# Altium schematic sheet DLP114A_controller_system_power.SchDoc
size 558 x 431 mm; Date: Not shown in title block; ApprovedBy: Not shown in title block; CheckedBy: Not shown in title block; Author: Not shown in title block; CompanyName: Not shown in title block; Engineer: Not shown in title block; Organization: Not shown in title block; Address1: Not shown in title block; Address2: Not shown in title block; Address3: Not shown in title block; Address4: Not shown in title block; DocumentNumber: 1; Revision: Use project parameter SCH_Rev; SheetNumber: 1; SheetTotal: 7; PageSetup: Record=PageOptions¦CenterHorizontal=True¦CenterVertical=True¦PrintScale=0.69¦XCorrection=1.00¦YCorrection=1.00¦PrintKind=0¦BorderSize=5000000¦LeftOffset=0¦BottomOffset=0¦Orientation=2¦PaperLength=1000¦PaperWidth=1000¦Scale=100¦PaperSource=15¦PrintQuality=600¦MediaType=1¦DitherType=10¦PaperKind=Letter¦PrintScaleMode=1
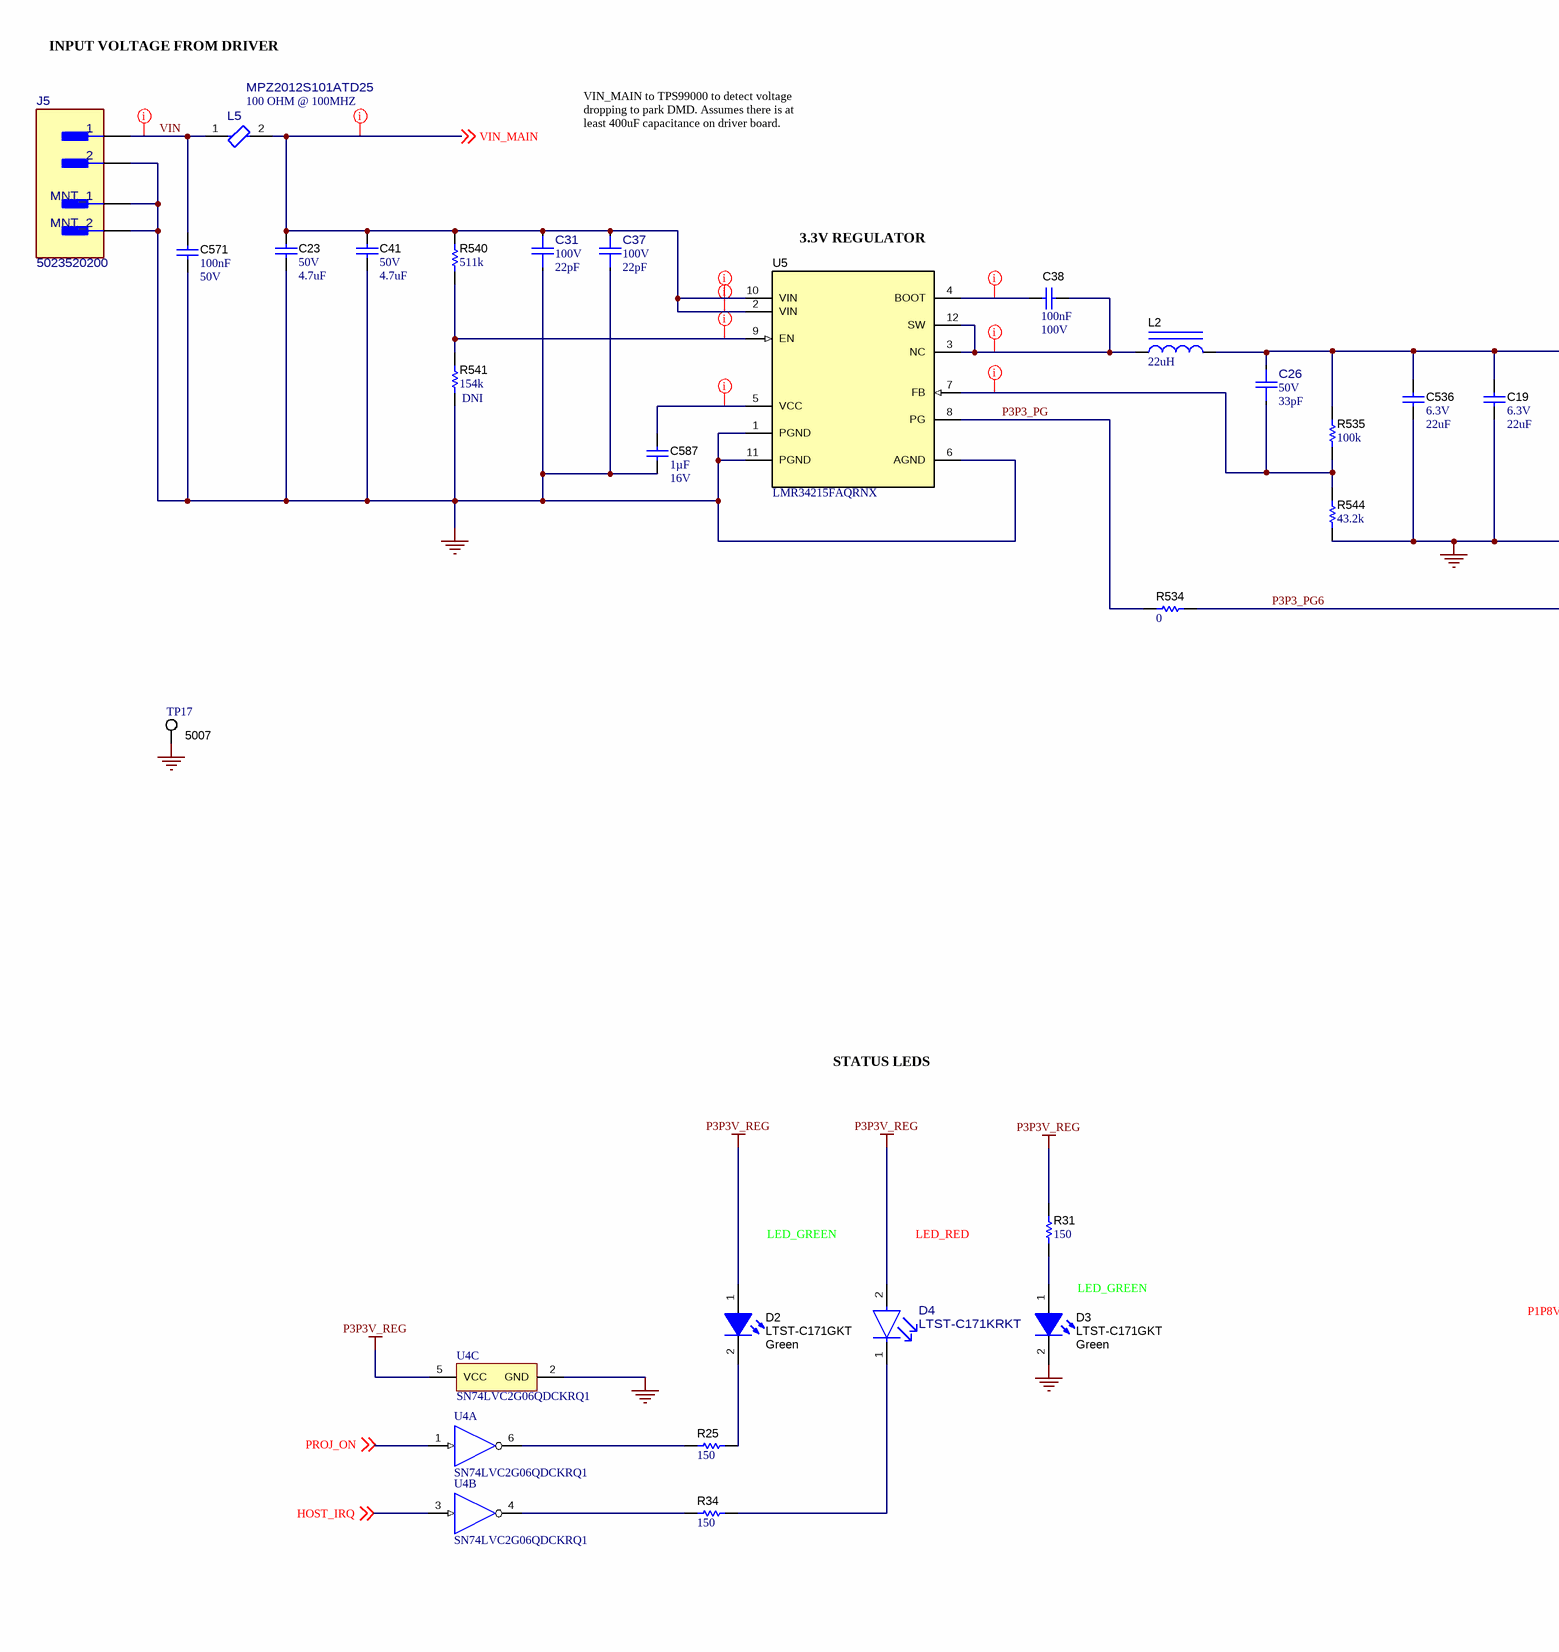
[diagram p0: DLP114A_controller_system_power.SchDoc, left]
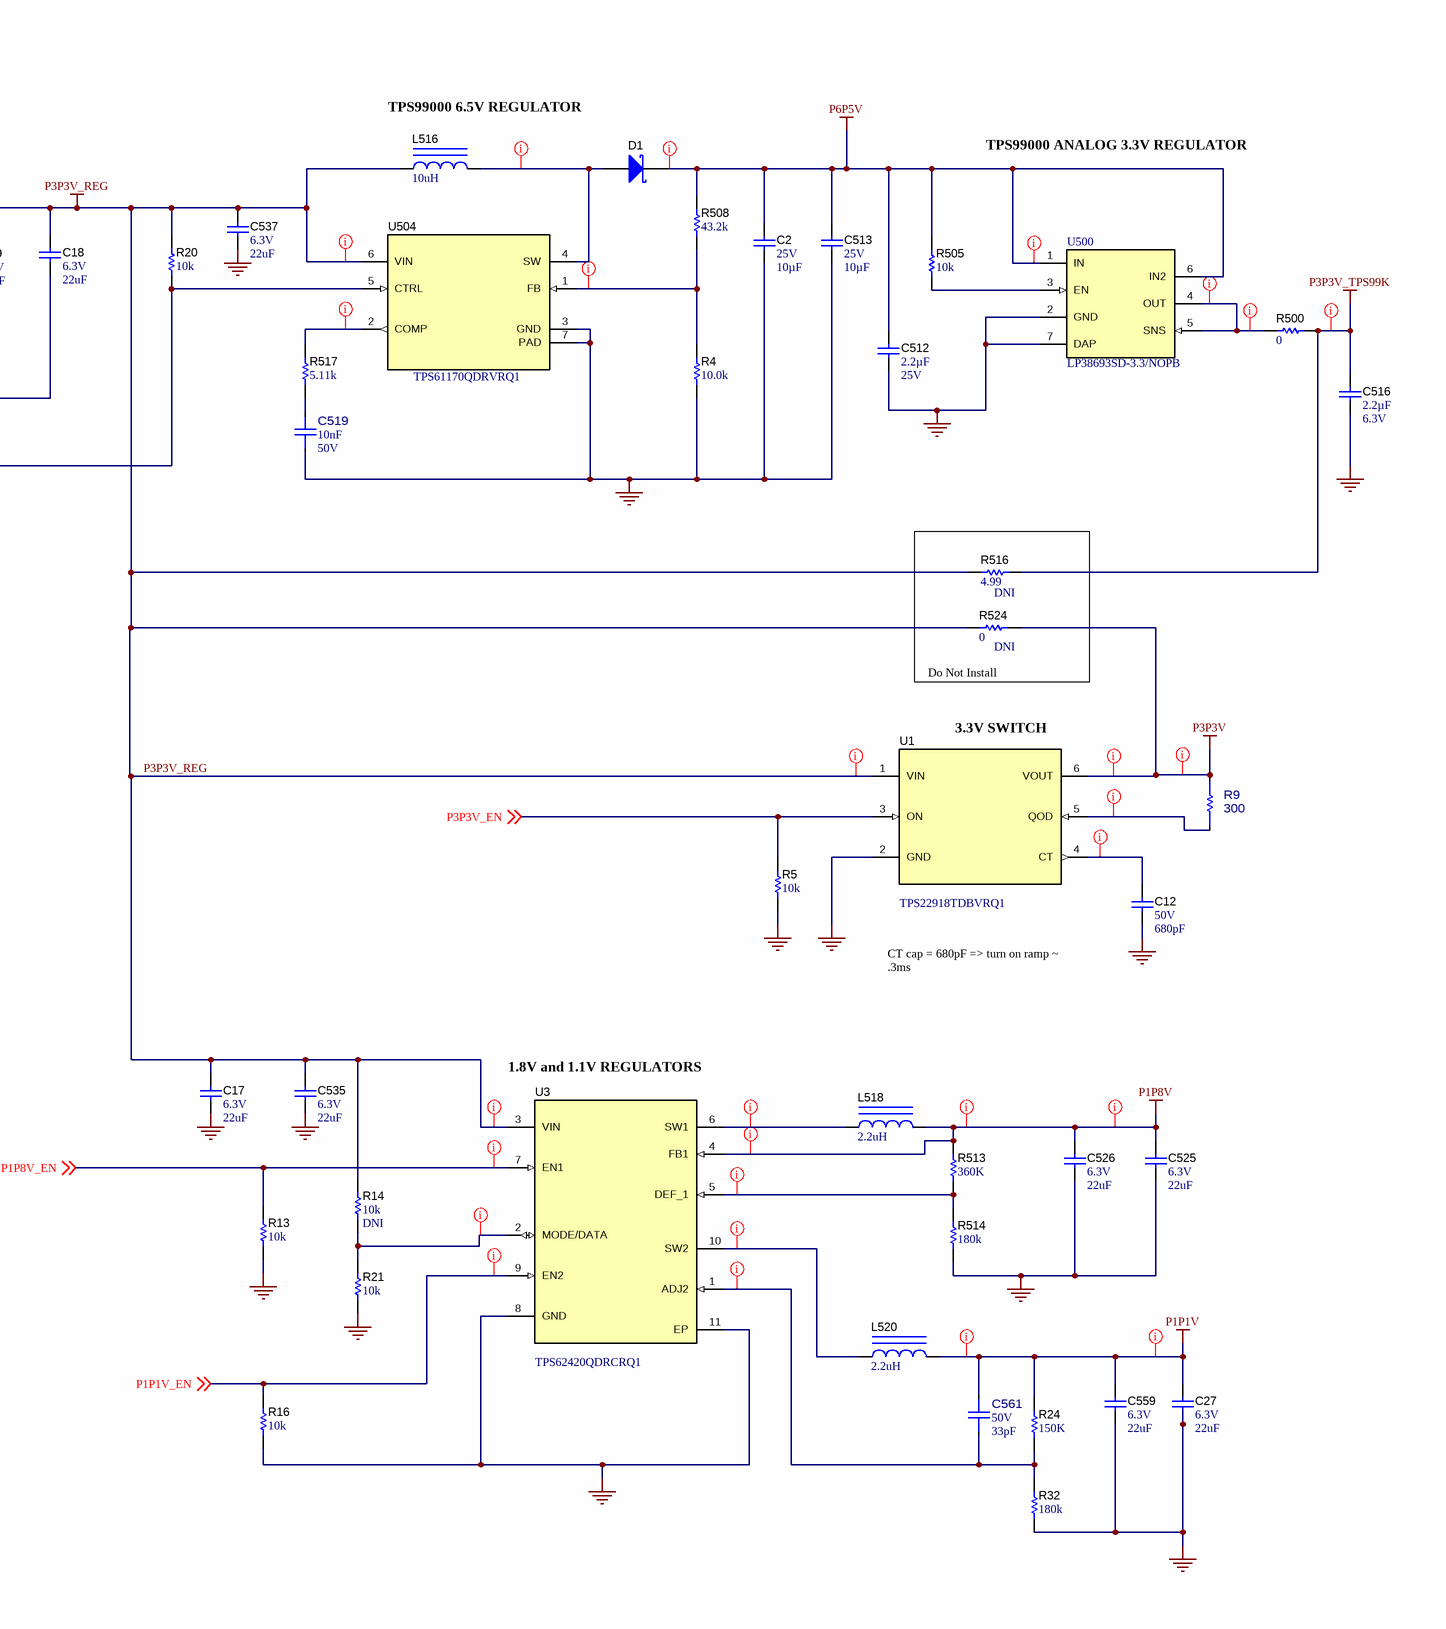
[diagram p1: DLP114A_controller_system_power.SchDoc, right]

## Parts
C2  VDC_V: 25V  ValueDisplayed: 10µF  [1206_180]  (hidden comment: C1206C106J3RACAUTO)
C12  VDC_V: 50V  ValueDisplayed: 680pF  [0402]  (hidden comment: GCM1555C1H681FA16D)
C17  VDC_V: 6.3V  ValueDisplayed: 22uF  [1206_180]  (hidden comment: GCM31CR70J226KE23L)
C18  VDC_V: 6.3V  ValueDisplayed: 22uF  [1206_180]  (hidden comment: GCM31CR70J226KE23L)
C19  VDC_V: 6.3V  ValueDisplayed: 22uF  [1206_180]  (hidden comment: GCM31CR70J226KE23L)
C23  VDC_V: 50V  ValueDisplayed: 4.7uF  [1210_280]  (hidden comment: CGA6P3X7R1H475M250AB)
C26  VDC_V: 50V  ValueDisplayed: 33pF  [FP-CGA3E2C0G1H330J080AA_0603-MFG]  (hidden comment: CGA3E2C0G1H330J080AA)
C27  VDC_V: 6.3V  ValueDisplayed: 22uF  [1206_180]  (hidden comment: GCM31CR70J226KE23L)
C31  VDC_V: 100V  Cap_F: 22pF  [FP-C0603C223K1RACAUTO_0603-MFG]  (hidden comment: C0603C223K1RACAUTO)
C37  VDC_V: 100V  Cap_F: 22pF  [FP-C0603C223K1RACAUTO_0603-MFG]  (hidden comment: C0603C223K1RACAUTO)
C38  Cap_F: 100nF  VDC_V: 100V  [0805_HV]  (hidden comment: GCM21BR72A104KA37L)
C41  VDC_V: 50V  ValueDisplayed: 4.7uF  [1210_280]  (hidden comment: CGA6P3X7R1H475M250AB)
C512  Cap_F: 2.2µF  VDC_V: 25V  [0805_HV]  (hidden comment: CGA4J3X7R1E225K125AB)
C513  VDC_V: 25V  ValueDisplayed: 10µF  [1206_180]  (hidden comment: C1206C106J3RACAUTO)
C516  Cap_F: 2.2µF  VDC_V: 6.3V  [0603]  (hidden comment: GCM188R70J225KE22D)
C519  ValueDisplayed: 10nF  VDC_V: 50V  [FP-GCM155R71H103KA55D_0402-MFG]  (hidden comment: GCM155R71H103KA55D)
C525  VDC_V: 6.3V  ValueDisplayed: 22uF  [1206_180]  (hidden comment: GCM31CR70J226KE23L)
C526  VDC_V: 6.3V  ValueDisplayed: 22uF  [1206_180]  (hidden comment: GCM31CR70J226KE23L)
C535  VDC_V: 6.3V  ValueDisplayed: 22uF  [1206_180]  (hidden comment: GCM31CR70J226KE23L)
C536  VDC_V: 6.3V  ValueDisplayed: 22uF  [1206_180]  (hidden comment: GCM31CR70J226KE23L)
C537  VDC_V: 6.3V  ValueDisplayed: 22uF  [1206_180]  (hidden comment: GCM31CR70J226KE23L)
C559  VDC_V: 6.3V  ValueDisplayed: 22uF  [1206_180]  (hidden comment: GCM31CR70J226KE23L)
C561  VDC_V: 50V  ValueDisplayed: 33pF  [FP-CGA3E2C0G1H330J080AA_0603-MFG]  (hidden comment: CGA3E2C0G1H330J080AA)
C571  Cap_F: 100nF  VDC_V: 50V  [0603]  (hidden comment: CGA3E2X7R1H104K080AA)
C587  Cap_F: 1µF  VDC_V: 16V  [0603]  (hidden comment: GCM188R71C105KA64D)
D1  PMEG10030ELPX  [SOD-128]  (value not drawn)
D2  LTST-C171GKT  value Green  [LED_LTST-C171]
D3  LTST-C171GKT  value Green  [LED_LTST-C171]
D4  LTST-C171KRKT  [FP-LTST-C171KRKT_0805-MFG]
J5  5023520200  [FP-5023520200_HDR2-MFG]
L2  ValueDisplayed: 22uH  [XAL5050]  (hidden comment: XAL5050-223MEB)
L5  MPZ2012S101ATD25  Parameter 1: 100 OHM @ 100MHZ  [FP-MPZ2012S101ATD25_0805-MFG]
L516  ValueDisplayed: 10uH  [CDRH5D18]  (hidden comment: CDRH5D18NP-100NC)
L518  ValueDisplayed: 2.2uH  [XFL4020]  (hidden comment: XFL4020-222MEB)
L520  ValueDisplayed: 2.2uH  [XFL4020]  (hidden comment: XFL4020-222MEB)
R4  ValueDisplayed: 10.0k  [0402]  (hidden comment: ERJ-2RKF1002X)
R5  ValueDisplayed: 10k  [0402]  (hidden comment: ERJ-2GEJ103X)
R9  300  [FP-ERJ-2RKF3000X_0402-MFG]
R13  ValueDisplayed: 10k  [0402]  (hidden comment: ERJ-2GEJ103X)
R14  ValueDisplayed: 10k  Parameter 1: DNI  [0402]  (hidden comment: ERJ-2GEJ103X)
R16  ValueDisplayed: 10k  [0402]  (hidden comment: ERJ-2GEJ103X)
R20  ValueDisplayed: 10k  [0402]  (hidden comment: ERJ-2GEJ103X)
R21  ValueDisplayed: 10k  [0402]  (hidden comment: ERJ-2GEJ103X)
R24  ValueDisplayed: 150K  [0402]  (hidden comment: ERJ-2RKF1503X)
R25  ValueDisplayed: 150  [0402]  (hidden comment: CRCW0402150RFKED)
R31  ValueDisplayed: 150  [0402]  (hidden comment: CRCW0402150RFKED)
R32  ValueDisplayed: 180k  [0402]  (hidden comment: RC0402FR-07180KL)
R34  ValueDisplayed: 150  [0402]  (hidden comment: CRCW0402150RFKED)
R500  ValueDisplayed: 0  [0402]  (hidden comment: CRCW04020000Z0EDHP)
R505  ValueDisplayed: 10k  [0402]  (hidden comment: ERJ-2GEJ103X)
R508  ValueDisplayed: 43.2k  [0402]  (hidden comment: CRCW040243K2FKED)
R513  ValueDisplayed: 360K  [0402]  (hidden comment: ERJ-2RKF3603X)
R514  ValueDisplayed: 180k  [0402]  (hidden comment: RC0402FR-07180KL)
R516  ValueDisplayed: 4.99  Parameter 1: DNI  [0402]  (hidden comment: CRCW04024R99FKED)
R517  ValueDisplayed: 5.11k  [0402]  (hidden comment: CRCW04025K11FKED)
R524  ValueDisplayed: 0  Parameter 1: DNI  [0402]  (hidden comment: CRCW04020000Z0EDHP)
R534  ValueDisplayed: 0  [0402]  (hidden comment: CRCW04020000Z0EDHP)
R535  ValueDisplayed: 100k  [0402]  (hidden comment: ERJ-2GEJ104X)
R540  ValueDisplayed: 511k  [0402]  (hidden comment: CRCW0402511KFKED)
R541  ValueDisplayed: 154k  Parameter 1: DNI  [0402]  (hidden comment: ERJ-2RKF1543X)
R544  ValueDisplayed: 43.2k  [0402]  (hidden comment: CRCW040243K2FKED)
TP17  5007  [Keystone5007]
U1  TPS22918TDBVRQ1  [DBV0006A_N]
U3  TPS62420QDRCRQ1  [DRC0010J]
U4  SN74LVC2G06QDCKRQ1  [DCK0006A_N]  (parts A,B,C of 3)
U5  LMR34215FAQRNX  [RNX0012B]
U500  LP38693SD-3.3/NOPB  [NGG0006A]
U504  TPS61170QDRVRQ1  [DRV0006A]

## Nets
GND: C2.2 C12.2 C17.2 C18.2 C19.2 C23.2 C27.2 C31.1 C37.1 C41.2 C512.2 C513.2 C516.2 C519.1 C525.2 C526.2 C535.2 C536.2 C537.2 C559.2 C571.2 C587.2 D3.2(K) J5.2 J5.3(MNT_1) J5.4(MNT_2) R4.1 R5.1 R13.1 R16.1 R21.1 R32.1 R514.1 R541.1 R544.1 TP17.1 U1.2(GND) U3.8(GND) U3.11(EP) U4.2(GND) U5.1(PGND) U5.6(AGND) U5.11(PGND) U500.2(GND) U500.7(DAP) U504.3(GND) U504.7(PAD)
P1P1V: C27.1 C559.1 C561.2 L520.2 R24.2
P1P8V: C525.1 C526.1 L518.2 R513.2 U3.4(FB1)
P3P3V: R9.2 R524.2 U1.6(VOUT)
P3P3V_REG: C17.1 C18.1 C19.1 C26.2 C535.1 C536.1 C537.1 D2.1(A) D4.2(ANODE) L2.2 L516.1 R14.2 R20.2 R31.2 R516.1 R524.1 R535.2 U1.1(VIN) U3.3(VIN) U4.5(VCC) U504.6(VIN)
P3P3V_TPS99K: C516.1 R500.2 R516.2
P6P5V: C2.1 C512.1 C513.1 D1.1(K) R505.2 R508.2 U500.1(IN) U500.6(IN2)
HOST_IRQ: U4.3(2A) ; off-sheet HOST_IRQ
P1P1V_EN: R16.2 U3.9(EN2) ; off-sheet P1P1V_EN
P1P8V_EN: R13.2 U3.7(EN1) ; off-sheet P1P8V_EN
P3P3_PG: R534.1 U5.8(PG)
P3P3_PG6: R20.1 R534.2 U504.5(CTRL)
P3P3V_EN: R5.2 U1.3(ON) ; off-sheet P3P3V_EN
PROJ_ON: U4.1(1A) ; off-sheet PROJ_ON
VIN: C571.1 J5.1 L5.1
VIN_MAIN: C23.1 C31.2 C37.2 C41.1 L5.2 R540.2 U5.2(VIN) U5.10(VIN) ; off-sheet VIN_MAIN
NetC12_1: C12.1 U1.4(CT)
NetC26_1: C26.1 R535.1 R544.2 U5.7(FB)
NetC38_1: C38.1 L2.1 U5.3(NC) U5.12(SW)
NetC38_2: C38.2 U5.4(BOOT)
NetC519_2: C519.2 R517.1
NetC561_1: C561.1 R24.1 R32.2 U3.1(ADJ2)
NetC587_1: C587.1 U5.5(VCC)
NetD1_2: D1.2(A) L516.2 U504.4(SW)
NetD2_2: D2.2(K) R25.1
NetD3_1: D3.1(A) R31.1
NetD4_1: D4.1(CATHODE) R34.1
NetL518_1: L518.1 U3.6(SW1)
NetL520_1: L520.1 U3.10(SW2)
NetR4_2: R4.2 R508.1 U504.1(FB)
NetR9_1: R9.1 U1.5(QOD)
NetR14_1: R14.1 R21.2 U3.2(MODE/DATA)
NetR25_2: R25.2 U4.6(1Y)
NetR34_2: R34.2 U4.4(2Y)
NetR500_1: R500.1 U500.4(OUT) U500.5(SNS)
NetR505_1: R505.1 U500.3(EN)
NetR513_1: R513.1 R514.2 U3.5(DEF_1)
NetR517_2: R517.2 U504.2(COMP)
NetR540_1: R540.1 R541.2 U5.9(EN)

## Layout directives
net class 50OHM: NetC12_1, NetR4_2, NetR14_1, NetR513_1, NetR517_2, NetR540_1, P1P1V_EN, P1P8V_EN
net class POWER: NetC26_1, NetC38_1, NetC38_2, NetC561_1, NetC587_1, NetD1_2, NetL518_1, NetL520_1, NetR9_1, NetR500_1, P1P1V, P1P8V, P3P3V, P3P3V_REG, P3P3V_TPS99K, P6P5V, VIN, VIN_MAIN
net class Voltage Spacing (15Mils): P1P1V, P1P8V, P3P3V

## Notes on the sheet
- INPUT VOLTAGE FROM DRIVER
- VIN_MAIN to TPS99000 to detect voltage
  dropping to park DMD. Assumes there is at
  least 400uF capacitance on driver board.
- 3.3V REGULATOR
- TPS99000 6.5V REGULATOR
- TPS99000 ANALOG 3.3V REGULATOR
- (near R524) Do Not Install
- (near U1) 3.3V SWITCH
- STATUS LEDS
- (near C12) CT cap = 680pF => turn on ramp ~
  .3ms
  QOD resistor = 300 ohms => turn off ramp ~|.6ms
- 1.8V and 1.1V REGULATORS
- LED_GREEN
- LED_RED

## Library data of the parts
C2 C513 = CMP-0081062-1: CAP, CERM, 10 µF, 25 V,+/- 5%, X7R, AEC-Q200 Grade 1, 1206; Manufacturer: Kemet; TaMin_C: -55°C; Polarized: N; SizeAreaWB_mm2: 10.92; U/M: EA; Value: 10uF; TaMax_C: 125°C; SizeZ_mm: 1.8; SizeX_mm: 3.2; SizeY_mm: 1.6; SizeArea_mm2: 5.12; AEC Qualified: Y; AEC Grade: 1; AEC Category: Q200
C12 = CMP-0086096-1: CAP, CERM, 680 pF, 50 V,+/- 1%, C0G/NP0, AEC-Q200 Grade 1, 0402; Manufacturer: MuRata; SizeArea_mm2: 0.5; Polarized: N; SizeZ_mm: 0.6; SizeAreaWB_mm2: 3; AEC Qualified: Y; Value: 680pF; TaMin_C: -55°C; SizeX_mm: 1; U/M: EA; TaMax_C: 125°C; AEC Category: Q200
C17-C19 C27 C525 C526 C535-C537 C559 = CMP-0008809-2: CAP, CERM, 22 uF, 6.3 V, +/- 10%, X7R, AEC-Q200 Grade 1, 1206; Manufacturer: MuRata; TaMin_C: -55°C; Polarized: N; SizeAreaWB_mm2: 10.92; Value1: Unknown; U/M: EA; Value: 22uF; TaMax_C: 125°C; SizeZ_mm: 1.8; SizeX_mm: 3.2; SizeY_mm: 1.6; Cap_Case: 1206; SizeArea_mm2: 5.12; AEC Qualified: Y; Cap_F: 22µF; AEC Grade: 1; AEC Category: Q200
C23 C41 = CMP-0009163-2: CAP, CERM, 4.7 uF, 50 V, +/- 20%, X7R, AEC-Q200 Grade 1, 1210; Manufacturer: TDK; TaMin_C: -55°C; Polarized: N; SizeAreaWB_mm2: 14.7; Value1: Unknown; U/M: EA; Value: 4.7uF; TaMax_C: 125°C; SizeZ_mm: 2.8; SizeX_mm: 3.2; SizeY_mm: 2.5; Cap_Case: 1210; SizeArea_mm2: 8; AEC Qualified: Y; Cap_F: 4.7µF; AEC Grade: 1; AEC Category: Q200
C26 C561 = CMP-0095622-1: Cap Ceramic 33pF 50V C0G 5% Pad SMD 0603 +125°C Automotive T/R; Manufacturer: TDK; SizeZ_mm: 1.1mm; AEC Grade: Grade 1; Tolerance_%: 0.05%; AEC Qualified: Yes; TempCo: 30ppm/°C
C31 C37 = CMP-0095620-1: C0603 22,000 pF X7R 30ppm/°C 10.00% 100 V; Manufacturer: KEMET; AEC Grade: Grade 1; Value: 22pF; SizeZ_mm: 0.87mm; Tolerance_%: 0.1%; AEC Qualified: Yes
C38 = CMP-0860440-1: CAP, CERM, 0.1 µF, 100 V,+/- 10%, X7R, AEC-Q200 Grade 1, 0805; Manufacturer: MuRata; SizeY_mm: 1.25; ValueDisplayed: 0.1µF; SizeX_mm: 2; Cap_Case: 0805; AEC Grade: 1; Polarized: N; Value: 0.1uF; TaMin_C: -55°C; SizeZ_mm: 1.45; TaMax_C: 125°C; U/M: EA; SizeArea_mm2: 2.5; AEC Qualified: Y; SizeAreaWB_mm2: 6.75; AEC Category: Q200
C512 = CMP-0007975-2: CAP, CERM, 2.2 uF, 25 V, +/- 10%, X7R, AEC-Q200 Grade 1, 0805; Manufacturer: TDK; TaMin_C: -55°C; Polarized: N; SizeAreaWB_mm2: 6.75; Value1: Unknown; U/M: EA; Value: 2.2uF; TaMax_C: 125°C; SizeZ_mm: 1.45; SizeX_mm: 2; SizeY_mm: 1.25; Cap_Case: 0805; SizeArea_mm2: 2.5; AEC Qualified: Y; AEC Grade: 1; AEC Category: Q200
C516 = CMP-0007134-5: CAP, CERM, 2.2 uF, 6.3 V, +/- 10%, X7R, AEC-Q200 Grade 1, 0603; Manufacturer: MuRata; TaMin_C: -55°C; Polarized: N; SizeAreaWB_mm2: 4.68; Value1: Unknown; U/M: EA; Value: 2.2uF; TaMax_C: 125°C; SizeZ_mm: 1; SizeX_mm: 1.6; SizeY_mm: 0.8; SizeArea_mm2: 1.28; AEC Qualified: Y; AEC Category: Q200
C519 = CMP-0093287-1: Ceramic Capacitor for Automotive 10nF ±10% 50VDC X7R 0402 Paper T/R; Manufacturer: Murata; AEC Qualified: Yes; Tolerance_%: 0.1%; SizeZ_mm: 0.55mm; TempCo: 15%; AEC Grade: Grade 1
C571 = CMP-0007078-4: CAP, CERM, 0.1 uF, 50 V, +/- 10%, X7R, AEC-Q200 Grade 1, 0603; Manufacturer: TDK; TaMin_C: -55°C; ESR_ohm: 0.0296; Polarized: N; SizeAreaWB_mm2: 4.68; Value1: 0.0296 ohm; U/M: EA; Value: 0.1uF; TaMax_C: 125°C; SizeZ_mm: 1; SizeX_mm: 1.6; SizeY_mm: 0.8; SizeArea_mm2: 1.28; AEC Qualified: Y; IRMS_A: 9.7199dA; AEC Category: Q200
C587 = CMP-0007136-5: CAP, CERM, 1 uF, 16 V, +/- 10%, X7R, AEC-Q200 Grade 1, 0603; Manufacturer: MuRata; TaMin_C: -55°C; Polarized: N; SizeAreaWB_mm2: 4.68; Value1: Unknown; U/M: EA; Value: 1uF; TaMax_C: 125°C; SizeZ_mm: 1; SizeX_mm: 1.6; SizeY_mm: 0.8; SizeArea_mm2: 1.28; AEC Qualified: Y; AEC Category: Q200
D1 = CMP-0028783-3: Diode, Schottky, 100 V, 3 A, AEC-Q101, SOD-128; Manufacturer: Nexperia; Io_A: 3A; Vr_V: 100V; Value2: 0.77V; Vf_V: 770mV; SizeY_mm: 2.5; Value: 100V; Green_Lifecycle: Not Set; SizeZ_mm: 1.1; Green_REACh: Incomplete; TJmax_C: 175°C; AEC Qualified: Y; AEC Category: Q101; SizeX_mm: 4.6; SizeAreaWB_mm2: 19.6; SizeArea_mm2: 11.5
D2 D3 = CMP-0002830-3: LED, Green, SMD; Manufacturer: Lite-On; SizeArea_mm2: 2.5; SizeZ_mm: 1.2; Vf_V: 2.1V; SizeAreaWB_mm2: 6.75; Value1: W; SizeX_mm: 2; Type: AlInGaP; SizeY_mm: 1.25; Io_A: 20A
D4 = CMP-0095628-1: Red 631nm LED Indication - Discrete 2V 0805 (2012 Metric); Manufacturer: Lite-On; LambdaP: 639nm; Vr_V: 5V; AEC Qualified: No; Led Orientation: Top View; Luminous Intensity: 54mcd; Power_TotalModule: 75mW; SizeZ_mm: 0.9mm; Forward Current: 20mA; Angle: 130°
J5 = CMP-0089653-1: Connector Header Surface Mount, Right Angle 2 position 0.079" (2.00mm); Manufacturer: Molex; SizeZ_mm: 6.6mm; Conn Gender: Male; Current_A: 3A; TaMin_C: -40°C; DUT-Pitch_mm: 2mm; TaMax_C: +105°C; Row_Count: 1; AEC Qualified: No; ContactFinish: Gold,Nickel; Voltage_V: 125V
L2 = CMP-0061651-2: Inductor, Shielded, Composite, 22 uH, 3.4 A, 0.1 ohm, SMD; Manufacturer: Coilcraft; Isat: 3.6A @ 30% inductance drop; Irms: 3.4A @ 40C rise; Green_Lifecycle: Not Set; SizeAreaWB_mm2: 54.4544; DCR_ohm: 1d; Green_REACh: Incomplete; Value1: 0.1 ohm; Value: 22uH; Imax_A: 3.4A; SizeZ_mm: 5.1; SizeX_mm: 5.28; SizeY_mm: 5.48; SizeArea_mm2: 28.9344; Ind_H: 22µH; AEC Category: Q200
L5 = CMP-0089947-1: 100 Ohms @ 100MHz 1 Power Line Ferrite Bead 0805 (2012 Metric) 4A 20mOhm; Manufacturer: TDK; AEC Qualified: Yes; AEC Grade: Grade 1; DCR_ohm: 20m; Impedance At Frequency: 100Ω @ 100MHz; Tolerance_%: 25%; SizeZ_mm: 1.05mm
L516 = CMP-0062263-1: Inductor, Shielded Drum Core, Ferrite, 10 uH, 1.2 A, 0.124 ohm, SMD; Manufacturer: Sumida; Isat: 1.2A @ 35% inductance drop; Irms: 1.2A @ 30C rise; Green_Lifecycle: Not Set; SizeAreaWB_mm2: 64; DCR_ohm: 0.124; Green_REACh: Incomplete; Value: 10uH; Imax_A: 1.2A; SizeZ_mm: 2; SizeX_mm: 6; SizeArea_mm2: 36; Ind_H: 10µH; AEC Category: Q200
L518 L520 = CMP-0061150-1: Inductor, Shielded, Composite, 2.2 uH, 3.7 A, 0.02 ohm, SMD; Manufacturer: Coilcraft; Isat: 3.7A @ 30% inductance drop; Irms: 8A @ 40C rise; Green_Lifecycle: Not Set; SizeAreaWB_mm2: 25; DCR_ohm: 0.02; Green_REACh: Incomplete; Value: 2.2uH; Imax_A: 3.7A; SizeZ_mm: 2.15; SizeX_mm: 4; SizeArea_mm2: 16; Ind_H: 2.2µH; AEC Category: Q200
R4 = CMP-0026658-1: RES, 10.0 k, 1%, 0.1 W, 0402; Manufacturer: Panasonic; Power_W: 100mW; TempCo: 100 ppm/C; Value_Code: 10k0; U/M: EA; Value: 10.0k; EIA_Code: E96; Res_ohm: 10k; SizeX_mm: 1; SizeY_mm: 0.5; SizeZ_mm: 0.6; Value2: 0.1W; VDC_V: 50V; AEC Category: Q200
R5 R13 R14 R16 R20 R21 R505 = CMP-0026994-4: RES, 10 k, 5%, 0.1 W, AEC-Q200 Grade 0, 0402; Manufacturer: Panasonic; Power_W: 100mW; TempCo: 200 ppm/C; Value_Code: 10k0; U/M: EA; Value: 10k; EIA_Code: E24; SizeX_mm: 1; SizeY_mm: 0.5; SizeZ_mm: 0.6; Value2: 0.1W; AEC Qualified: Y; VDC_V: 50V; AEC Grade: 0; AEC Category: Q200
R9 = CMP-0090161-1: 300 Ohms ±1% 0.1W, 1/10W Chip Resistor 0402 (1005 Metric) Automotive AEC-Q200 Thick Film; Part Number: ERJ-2RKF3000X; Manufacturer: Panasonic; SizeZ_mm: 0.4mm; AEC Qualified: Yes; Power_W: 100mW; AEC Grade: Grade 0; VDC_V: 50V; TempCo: 100ppm/°C
R24 = CMP-0026669-1: RES, 150 k, 1%, 0.1 W, AEC-Q200 Grade 0, 0402; Manufacturer: Panasonic; Power_W: 100mW; TempCo: 100 ppm/C; U/M: EA; Value: 150k; EIA_Code: E96; SizeX_mm: 1; SizeY_mm: 0.5; SizeZ_mm: 0.6; Value2: 0.1W; AEC Qualified: Y; VDC_V: 50V; AEC Grade: 0; AEC Category: Q200
R25 R31 R34 = CMP-0026022-3: RES, 150, 1%, 0.063 W, AEC-Q200 Grade 0, 0402; Manufacturer: Vishay-Dale; Power_W: 63mW; TempCo: 100 ppm/C; Value_Code: 150R; Value: 150; EIA_Code: E96; SizeX_mm: 1; SizeY_mm: 0.5; SizeZ_mm: 0.6; Value2: 0.063W; AEC Qualified: Y; VDC_V: 50V; AEC Category: Q200; AEC Grade: 0
R32 R514 = CMP-0026723-1: RES, 180 k, 1%, 0.063 W, 0402; Manufacturer: Yageo America; Power_W: 63mW; TempCo: 100 ppm/C; U/M: EA; Value: 180k; SizeX_mm: 1; SizeY_mm: 0.5; SizeZ_mm: 0.6; Value2: 0.063W; AEC Qualified: N; VDC_V: 50V; AEC Category: Q200
R500 R524 R534 = CMP-0081856-1: RES, 0, 0%, 0.2 W, AEC-Q200 Grade 0, 0402; Manufacturer: Vishay-Dale; SizeAreaWB_mm2: 3; SizeArea_mm2: 0.5; AEC Qualified: Y; AEC Category: Q200; Value: 0; SizeZ_mm: 0.6; Power_W: 200mW; VDC_V: 50V; Value2: 0.2W; SizeX_mm: 1
R508 R544 = CMP-0026379-2: RES, 43.2 k, 1%, 0.063 W, AEC-Q200 Grade 0, 0402; Manufacturer: Vishay-Dale; Power_W: 63mW; TempCo: 100 ppm/C; Value_Code: 43k2; Value: 43.2k; EIA_Code: E96; SizeX_mm: 1; SizeY_mm: 0.5; SizeZ_mm: 0.6; Value2: 0.063W; AEC Qualified: Y; VDC_V: 50V; AEC Category: Q200; AEC Grade: 0
R513 = CMP-0860333-1: RES, 360 k, 1%, 0.1 W, AEC-Q200 Grade 0, 0402; Manufacturer: Panasonic; SizeY_mm: 0.5; SizeZ_mm: 0.6; Value: 360k; AEC Category: Q200; SizeX_mm: 1; TempCo: 100 ppm/C; Value2: 0.1W; Power_W: 100mW; SizeAreaWB_mm2: 3; AEC Qualified: Y; AEC Grade: 0
R516 = CMP-0026434-2: RES, 4.99, 1%, 0.063 W, AEC-Q200 Grade 0, 0402; Manufacturer: Vishay-Dale; Power_W: 63mW; TempCo: 100 ppm/C; Value_Code: 4R99; Value: 4.99; EIA_Code: E96; SizeX_mm: 1; SizeY_mm: 0.5; SizeZ_mm: 0.6; Value2: 0.063W; AEC Qualified: Y; VDC_V: 50V; AEC Category: Q200; AEC Grade: 0
R517 = CMP-0026463-2: RES, 5.11 k, 1%, 0.063 W, AEC-Q200 Grade 0, 0402; Manufacturer: Vishay-Dale; Power_W: 63mW; TempCo: 100 ppm/C; Value_Code: 5k11; Value: 5.11k; EIA_Code: E96; SizeX_mm: 1; SizeY_mm: 0.5; SizeZ_mm: 0.6; Value2: 0.063W; AEC Qualified: Y; VDC_V: 50V; AEC Category: Q200; AEC Grade: 0
R535 = CMP-0026995-1: RES, 100 k, 5%, 0.1 W, AEC-Q200 Grade 0, 0402; Manufacturer: Panasonic; Power_W: 100mW; TempCo: 200 ppm/C; U/M: EA; Value: 100k; EIA_Code: E24; SizeX_mm: 1; SizeY_mm: 0.5; SizeZ_mm: 0.6; Value2: 0.1W; AEC Qualified: Y; VDC_V: 50V; AEC Grade: 0; AEC Category: Q200
R540 = CMP-0026435-2: RES, 511 k, 1%, 0.063 W, AEC-Q200 Grade 0, 0402; Manufacturer: Vishay-Dale; Power_W: 63mW; TempCo: 100 ppm/C; Value: 511k; EIA_Code: E96; SizeX_mm: 1; SizeY_mm: 0.5; SizeZ_mm: 0.6; Value2: 0.063W; AEC Qualified: Y; VDC_V: 50V; AEC Category: Q200; AEC Grade: 0
R541 = CMP-0026670-1: RES, 154 k, 1%, 0.1 W, AEC-Q200 Grade 0, 0402; Manufacturer: Panasonic; Power_W: 100mW; TempCo: 100 ppm/C; U/M: EA; Value: 154k; EIA_Code: E96; SizeX_mm: 1; SizeY_mm: 0.5; SizeZ_mm: 0.6; Value2: 0.1W; AEC Qualified: Y; VDC_V: 50V; AEC Grade: 0; AEC Category: Q200
TP17 = CMP-0055144-2: Test Point, Compact, White, TH; Manufacturer: Keystone Electronics; Green_Lifecycle: Active; Green_REACh: Passed; ContactFinish: Silver; CNHeader: FALSE; CT: TRUE
U1 = CMP-0081996-1: 5.5V, 2A, 52mΩ Automotive High-Side Load Switch with Adjustable Rise Time & Quick Output Discharge, DBV0006A (SOT-23-6); Alternate PartNumber: TPS22918TDBVTQ1; Alternate Manufacturer: Texas Instruments; SizeAreaWB_mm2: 14.82; SizeZ_mm: 1.45; SizeX_mm: 2.8; SizeY_mm: 2.9; SizeArea_mm2: 8.12; CompType: IC; AEC Qualified: Y; AEC Category: Q200
U3 = CMP-0074044-5: Automotive 2.5V to 6V, 2.25MHz Fixed Frequency Dual (1A/600mA) Buck Converter with 1-Wire Interface, DRC0010J (VSON-10); Manufacturer: Texas Instruments; SizeX_mm: 3; SizeZ_mm: 1; AEC Category: Q200; AEC Qualified: Y; SizeArea_mm2: 9; SizeAreaWB_mm2: 16; CompType: IC
U4 = CMP-0051776-3: Automotive Catalog Dual Inverter Buffer/Driver with Open-Drain Output, DCK0006A (SOT-SC70-6); Manufacturer: Texas Instruments; Generic Part Number: SN74LVC2G06-Q1; Output Type: CMOS; Bits(#): 2; Input Type: CMOS/TTL; Technology Family: LVC; Schmitt Trigger: No; VCC(Max)(V): 5.5; Output Drive (IOL/IOH)(Max)(mA): 32/-32; ICC @ Nom Voltage(Max)(mA): 0.01; VCC(Min)(V): 1.65; F @ Nom Voltage(Max)(Mhz): 150; Logic: Inverting; Voltage(Nom)(V): 1.8,2.5,3.3,5; tpd @ Nom Voltage(Max)(ns): 7.2,3.9,3.4,2.9; AEC Category: Q200; AEC Qualified: Y; CompType: IC; SizeAreaWB_mm2: 9.3; SizeArea_mm2: 4.2; SizeX_mm: 2.1; SizeY_mm: 2.0; SizeZ_mm: 1.1
U5 = CMP-0860015-2: LMR342XX-Q1 SIMPLE SWITCHER® 42 V, 600mA/1.5A Synchronous Buck Converter, RNX0012B (VQFN-HR-12); Manufacturer: Texas Instruments; SizeArea_mm2: 6; SizeZ_mm: 0.9; CompType: IC; SizeY_mm: 3; SizeX_mm: 2; AEC Qualified: Y; SizeAreaWB_mm2: 12; AEC Category: Q200
U500 = CMP-0070711-3: 500mA Low Dropout CMOS Linear Regulators Stable with Ceramic Output Capacitors, 6-pin LLP, Pb-Free, 1000 Reel; Manufacturer: Texas Instruments; PackageTopMarking: ZXYTT*L130B; CompType: LDO IC; PowerWise: Y
U504 = CMP-0074076-5: Automotive Catalog 1.2A Switch, High Voltage Boost Converter in 2x2mm QFN Package, DRV0006A (WSON-6); Manufacturer: Texas Instruments; SizeX_mm: 2; CompType: IC; SizeZ_mm: 0.8; SizeArea_mm2: 4; SizeAreaWB_mm2: 9; U/M: EA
